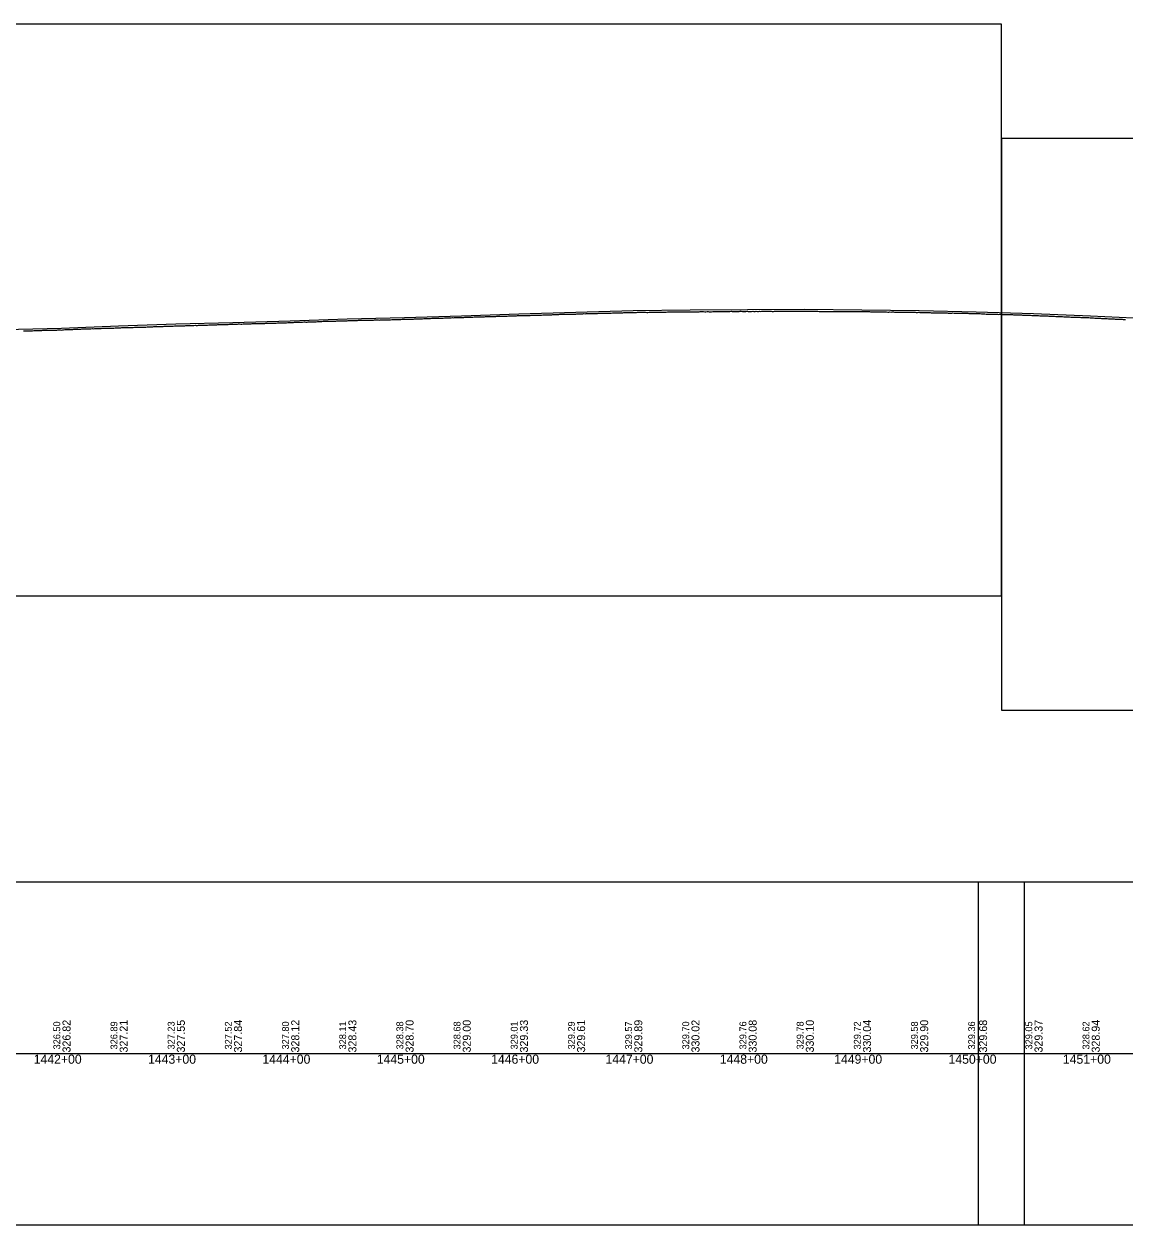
# Model space of a CAD drawing. Extents: x 2898 to 49495, y -15038 to -13538.
# Drawn here: x 33621 to 34583, y -15038 to -13988 of the extents above; entities that cross this region are included whole.
import ezdxf

# ---------------------------------------------------------------- set-up
doc = ezdxf.new("R2010")
doc.units = 0
for name, color, linetype in [('RD_DDB_Profile_EX', 7, 'Continuous'), ('RD_DDB_Profile_PR', 7, 'Continuous'), ('RD_DDB_StaTX', 7, 'Continuous'), ('RD_DDB_StripGrade', 7, 'Continuous'), ('RD_GPK_Profile_Cell', 7, 'Continuous'), ('RD_SHT_ShtClip', 7, 'Continuous')]:
    doc.layers.add(name, color=color, linetype=linetype)

msp = doc.modelspace()

# ---------------------------------------------------------------- linework, layer by layer
at = {"layer": 'RD_DDB_Profile_EX'}
for points in [[(33858.3, -14249.1), (33859.3, -14249.1), (33860.3, -14249.1), (33861.3, -14249.1), (33862.3, -14249.1), (33863.3, -14249.1), (33864.3, -14249), (33865.3, -14248.9), (33866.3, -14248.9), (33867.3, -14249), (33868.3, -14249), (33869.3, -14248.9), (33870.3, -14248.8), (33871.3, -14248.7), (33872.3, -14248.7), (33873.3, -14248.7), (33874.3, -14248.7), (33875.3, -14248.8), (33876.3, -14248.7), (33877.3, -14248.6), (33878.3, -14248.6), (33879.3, -14248.6), (33880.3, -14248.5), (33881.3, -14248.5), (33882.3, -14248.4), (33883.3, -14248.4), (33884.3, -14248.4), (33885.3, -14248.4), (33886.3, -14248.4), (33887.3, -14248.2), (33888.3, -14248.3), (33889.3, -14248.3), (33890.3, -14248.3), (33891.3, -14248.2), (33892.3, -14248.2), (33893.3, -14248.2), (33894.3, -14248.1), (33895.3, -14248), (33896.3, -14248), (33897.3, -14248), (33898.3, -14248), (33899.3, -14248), (33900.3, -14248), (33901.3, -14247.9), (33902.3, -14247.9), (33903.3, -14247.9), (33904.3, -14247.8), (33905.3, -14247.8), (33906.3, -14247.8), (33907.3, -14247.8), (33908.3, -14247.8), (33909.3, -14247.8), (33910.3, -14247.8), (33911.3, -14247.7), (33912.3, -14247.7), (33913.3, -14247.5), (33914.3, -14247.5), (33915.3, -14247.5), (33916.3, -14247.4), (33917.3, -14247.5), (33918.3, -14247.5), (33919.3, -14247.4), (33920.3, -14247.4), (33921.3, -14247.4), (33922.3, -14247.4), (33923.3, -14247.4), (33924.3, -14247.3), (33925.3, -14247.4), (33926.3, -14247.3), (33927.3, -14247.2), (33928.3, -14247.2), (33929.3, -14247.2), (33930.3, -14247.2), (33931.3, -14247.3), (33932.3, -14247.1), (33933.3, -14247.1), (33934.3, -14247.1), (33935.3, -14247.1), (33936.3, -14247.1), (33937.3, -14247), (33938.3, -14247), (33939.3, -14247.1), (33940.3, -14247.1), (33941.3, -14247), (33942.3, -14246.9), (33943.3, -14246.9), (33944.3, -14246.9), (33945.3, -14246.9), (33946.3, -14246.9), (33947.3, -14246.8), (33948.3, -14246.8), (33949.3, -14246.7), (33950.3, -14246.7), (33951.3, -14246.6), (33952.3, -14246.6), (33953.3, -14246.6), (33954.3, -14246.6), (33955.3, -14246.6), (33956.3, -14246.5), (33957.3, -14246.5), (33958.3, -14246.5)], [(33958.3, -14246.5), (33959.3, -14246.5), (33960.3, -14246.4), (33961.3, -14246.4), (33962.3, -14246.3), (33963.3, -14246.3), (33964.3, -14246.2), (33965.3, -14246.2), (33966.3, -14246.2), (33967.3, -14246.1), (33968.3, -14246.1), (33969.3, -14246.1), (33970.3, -14246), (33971.3, -14246), (33972.3, -14246), (33973.3, -14245.9), (33974.3, -14245.9), (33975.3, -14245.8), (33976.3, -14245.8), (33977.3, -14245.7), (33978.3, -14245.6), (33979.3, -14245.7), (33980.3, -14245.6), (33981.3, -14245.6), (33982.3, -14245.6), (33983.3, -14245.6), (33984.3, -14245.5), (33985.3, -14245.5), (33986.3, -14245.5), (33987.3, -14245.5), (33988.3, -14245.4), (33989.3, -14245.4), (33990.3, -14245.4), (33991.3, -14245.4), (33992.3, -14245.3), (33993.3, -14245.3), (33994.3, -14245.3), (33995.3, -14245.2), (33996.3, -14245.3), (33997.3, -14245.2), (33998.3, -14245.2), (33999.3, -14245.2), (34000.3, -14245.1), (34001.3, -14245.1), (34002.3, -14245.1), (34003.3, -14245.1), (34004.3, -14245), (34005.3, -14245), (34006.3, -14244.9), (34007.3, -14244.9), (34008.3, -14244.9), (34009.3, -14244.8), (34010.3, -14244.9), (34011.3, -14244.8), (34012.3, -14244.7), (34013.3, -14244.7), (34014.3, -14244.6), (34015.3, -14244.6), (34016.3, -14244.5), (34017.3, -14244.5), (34018.3, -14244.5), (34019.3, -14244.5), (34020.3, -14244.5), (34021.3, -14244.4), (34022.3, -14244.4), (34023.3, -14244.4), (34024.3, -14244.3), (34025.3, -14244.2), (34026.3, -14244.3), (34027.3, -14244.3), (34028.3, -14244.3), (34029.3, -14244.2), (34030.3, -14244.1), (34031.3, -14244.1), (34032.3, -14244.2), (34033.3, -14244.1), (34034.3, -14244), (34035.3, -14244), (34036.3, -14244), (34037.3, -14244), (34038.3, -14243.9), (34039.3, -14243.9), (34040.3, -14243.9), (34041.3, -14243.9), (34042.3, -14243.9), (34043.3, -14243.8), (34044.3, -14243.7), (34045.3, -14243.7), (34046.3, -14243.7), (34047.3, -14243.6), (34048.3, -14243.6), (34049.3, -14243.6), (34050.3, -14243.5), (34051.3, -14243.5), (34052.3, -14243.4), (34053.3, -14243.4), (34054.3, -14243.4), (34055.3, -14243.3), (34056.3, -14243.3), (34057.3, -14243.3), (34058.3, -14243.2)], [(34058.3, -14243.2), (34059.3, -14243.2), (34060.3, -14243.3), (34061.3, -14243.3), (34062.3, -14243.3), (34063.3, -14243.2), (34064.3, -14243.1), (34065.3, -14243.1), (34066.3, -14243.1), (34067.3, -14243.1), (34068.3, -14243.1), (34069.3, -14243.1), (34070.3, -14243), (34071.3, -14243), (34072.3, -14242.9), (34073.3, -14242.9), (34074.3, -14242.8), (34075.3, -14242.8), (34076.3, -14242.8), (34077.3, -14242.7), (34078.3, -14242.7), (34079.3, -14242.7), (34080.3, -14242.7), (34081.3, -14242.6), (34082.3, -14242.6), (34083.3, -14242.5), (34084.3, -14242.5), (34085.3, -14242.5), (34086.3, -14242.4), (34087.3, -14242.3), (34088.3, -14242.3), (34089.3, -14242.2), (34090.3, -14242.2), (34091.3, -14242.2), (34092.3, -14242.2), (34093.3, -14242.2), (34094.3, -14242.2), (34095.3, -14242.1), (34096.3, -14242.1), (34097.3, -14242), (34098.3, -14242.1), (34099.3, -14242.1), (34100.3, -14242), (34101.3, -14242), (34102.3, -14242), (34103.3, -14242), (34104.3, -14241.9), (34105.3, -14241.9), (34106.3, -14241.8), (34107.3, -14241.8), (34108.3, -14241.8), (34109.3, -14241.8), (34110.3, -14241.7), (34111.3, -14241.8), (34112.3, -14241.7), (34113.3, -14241.6), (34114.3, -14241.6), (34115.3, -14241.6), (34116.3, -14241.6), (34117.3, -14241.6), (34118.3, -14241.5), (34119.3, -14241.5), (34120.3, -14241.5), (34121.3, -14241.5), (34122.3, -14241.5), (34123.3, -14241.4), (34124.3, -14241.4), (34125.3, -14241.3), (34126.3, -14241.4), (34127.3, -14241.3), (34128.3, -14241.3), (34129.3, -14241.3), (34130.3, -14241.2), (34131.3, -14241.2), (34132.3, -14241.2), (34133.3, -14241.2), (34134.3, -14241.2), (34135.3, -14241.1), (34136.3, -14241.1), (34137.3, -14241.1), (34138.3, -14241.1), (34139.3, -14241), (34140.3, -14240.9), (34141.3, -14241), (34142.3, -14241), (34143.3, -14240.9), (34144.3, -14240.9), (34145.3, -14240.8), (34146.3, -14240.8), (34147.3, -14240.8), (34148.3, -14240.7), (34149.3, -14240.7), (34150.3, -14240.7), (34151.3, -14240.6), (34152.3, -14240.6), (34153.3, -14240.6), (34154.3, -14240.6), (34155.3, -14240.6), (34156.3, -14240.6), (34157.3, -14240.5), (34158.3, -14240.5)], [(34158.3, -14240.5), (34159.3, -14240.5), (34160.3, -14240.5), (34161.3, -14240.5), (34162.3, -14240.5), (34163.3, -14240.5), (34164.3, -14240.4), (34165.3, -14240.6), (34166.3, -14240.6), (34167.3, -14240.4), (34168.3, -14240.3), (34169.3, -14240.4), (34170.3, -14240.4), (34171.3, -14240.4), (34172.3, -14240.3), (34173.3, -14240.3), (34174.3, -14240.3), (34175.3, -14240.3), (34176.3, -14240.3), (34177.3, -14240.4), (34178.3, -14240.4), (34179.3, -14240.3), (34180.3, -14240.3), (34181.3, -14240.4), (34182.3, -14240.3), (34183.3, -14240.2), (34184.3, -14240.2), (34185.3, -14240.2), (34186.3, -14240.1), (34187.3, -14240.1), (34188.3, -14240.1), (34189.3, -14240.1), (34190.3, -14240.1), (34191.3, -14240.1), (34192.3, -14240.1), (34193, -14240.1), (34194, -14240.1), (34195, -14240.1), (34196, -14240.1), (34197, -14240), (34198, -14240), (34199, -14240), (34200, -14240), (34201, -14240.1), (34202, -14240), (34203, -14240), (34204, -14240), (34205, -14240), (34206, -14240), (34207, -14240), (34208, -14240.1), (34209, -14240.1), (34210, -14240), (34211, -14240), (34212, -14239.9), (34213, -14239.9), (34214, -14239.9), (34215, -14239.9), (34216, -14240), (34217, -14240), (34218, -14239.8), (34219, -14239.9), (34220, -14240), (34221, -14240), (34222, -14240), (34223, -14239.9), (34224, -14239.9), (34225, -14239.9), (34226, -14239.8), (34227, -14239.8), (34228, -14239.8), (34229, -14239.9), (34230, -14239.9), (34231, -14239.9), (34232, -14239.9), (34233, -14239.8), (34234, -14239.8), (34235, -14239.8), (34236, -14239.8), (34237, -14239.8), (34238, -14239.7), (34239, -14239.6), (34240, -14239.7), (34241, -14239.7), (34242, -14239.7), (34243, -14239.7), (34244, -14239.7), (34245, -14239.7), (34246, -14239.7), (34247, -14239.6), (34248, -14239.6), (34249, -14239.7), (34250, -14239.7), (34251, -14239.7), (34252, -14239.7), (34253, -14239.6), (34254, -14239.7), (34255, -14239.7), (34256, -14239.7), (34257, -14239.7), (34258, -14239.6)], [(34258, -14239.6), (34259, -14239.7), (34260, -14239.7), (34261, -14239.6), (34262, -14239.7), (34263, -14239.7), (34264, -14239.6), (34265, -14239.7), (34266, -14239.6), (34267, -14239.6), (34268, -14239.6), (34269, -14239.6), (34270, -14239.6), (34271, -14239.6), (34272, -14239.6), (34273, -14239.6), (34274, -14239.6), (34275, -14239.7), (34276, -14239.7), (34277, -14239.6), (34278, -14239.5), (34279, -14239.5), (34280, -14239.6), (34281, -14239.6), (34282, -14239.6), (34283, -14239.5), (34284, -14239.6), (34285, -14239.6), (34286, -14239.6), (34287, -14239.6), (34288, -14239.6), (34289, -14239.6), (34290, -14239.5), (34291, -14239.5), (34292, -14239.5), (34293, -14239.6), (34294, -14239.6), (34295, -14239.5), (34296, -14239.5), (34297, -14239.5), (34298, -14239.5), (34299, -14239.5), (34300, -14239.5), (34301, -14239.5), (34302, -14239.6), (34303, -14239.5), (34304, -14239.6), (34305, -14239.6), (34306, -14239.6), (34307, -14239.6), (34308, -14239.6), (34309, -14239.6), (34310, -14239.6), (34311, -14239.6), (34312, -14239.5), (34313, -14239.6), (34314, -14239.6), (34315, -14239.6), (34316, -14239.7), (34317, -14239.7), (34318, -14239.7), (34319, -14239.7), (34320, -14239.8), (34321, -14239.8), (34322, -14239.8), (34323, -14239.8), (34324, -14239.7), (34325, -14239.7), (34326, -14239.7), (34327, -14239.7), (34328, -14239.8), (34329, -14239.8), (34330, -14239.7), (34331, -14239.7), (34332, -14239.7), (34333, -14239.7), (34334, -14239.7), (34335, -14239.7), (34336, -14239.7), (34337, -14239.7), (34338, -14239.8), (34339, -14239.8), (34340, -14239.7), (34341, -14239.7), (34342, -14239.7), (34343, -14239.7), (34344, -14239.7), (34345, -14239.8), (34346, -14239.8), (34347, -14239.8), (34348, -14239.8), (34349, -14239.8), (34350, -14239.8), (34351, -14239.9), (34352, -14239.9), (34353, -14239.9), (34354, -14239.9), (34355, -14239.8), (34356, -14239.8), (34357, -14239.9), (34358, -14239.9)], [(34358, -14239.9), (34359, -14239.9), (34360, -14239.9), (34361, -14240), (34362, -14240), (34363, -14240), (34364, -14240), (34365, -14240), (34366, -14240), (34367, -14240), (34368, -14240), (34369, -14240.1), (34370, -14240.1), (34371, -14240.1), (34372, -14240.1), (34373, -14240.2), (34374, -14240.2), (34375, -14240.2), (34376, -14240.3), (34377, -14240.3), (34378, -14240.2), (34379, -14240.3), (34380, -14240.2), (34381, -14240.2), (34382, -14240.3), (34383, -14240.3), (34384, -14240.3), (34385, -14240.4), (34386, -14240.4), (34387, -14240.4), (34388, -14240.4), (34389, -14240.4), (34390, -14240.4), (34391, -14240.4), (34392, -14240.4), (34393, -14240.4), (34394, -14240.4), (34395, -14240.4), (34396, -14240.4), (34397, -14240.4), (34398, -14240.4), (34399, -14240.5), (34400, -14240.5), (34401, -14240.6), (34402, -14240.6), (34403, -14240.5), (34404, -14240.6), (34405, -14240.7), (34406, -14240.7), (34407, -14240.7), (34408, -14240.7), (34409, -14240.7), (34410, -14240.7), (34411, -14240.8), (34412, -14240.8), (34413, -14240.8), (34414, -14240.9), (34415, -14240.9), (34416, -14240.9), (34417, -14240.9), (34418, -14240.9), (34419, -14241), (34420, -14241), (34421, -14241), (34422, -14241), (34423, -14241), (34424, -14241), (34425, -14241), (34426, -14241), (34427, -14241.1), (34428, -14241.1), (34429, -14241.2), (34430, -14241.3), (34431, -14241.2), (34432, -14241.2), (34433, -14241.1), (34434, -14241.2), (34435, -14241.3), (34436, -14241.4), (34437, -14241.4), (34438, -14241.4), (34439, -14241.4), (34440, -14241.4), (34441, -14241.4), (34442, -14241.4), (34443, -14241.4), (34444, -14241.4), (34445, -14241.4), (34446, -14241.4), (34447, -14241.5), (34448, -14241.5), (34449, -14241.5), (34450, -14241.5), (34451, -14241.5), (34452, -14241.6), (34453, -14241.6), (34454, -14241.7), (34455, -14241.6), (34456, -14241.7), (34457, -14241.7), (34458, -14241.8)], [(34458, -14241.8), (34459, -14241.8), (34460, -14241.9), (34461, -14241.9), (34462, -14242), (34463, -14242), (34464, -14242), (34465, -14242), (34466, -14242), (34467, -14242), (34468, -14242), (34469, -14242.1), (34470, -14242.2), (34471, -14242.2), (34472, -14242.2), (34473, -14242.3), (34474, -14242.2), (34475, -14242.2), (34476, -14242.3), (34477, -14242.4), (34478, -14242.4), (34479, -14242.4), (34480, -14242.4), (34481, -14242.4), (34482, -14242.5), (34483, -14242.5), (34484, -14242.5), (34485, -14242.5), (34486, -14242.6), (34487, -14242.6), (34488, -14242.6), (34489, -14242.7), (34490, -14242.8), (34491, -14242.7), (34492, -14242.8), (34493, -14242.8), (34494, -14242.9), (34495, -14242.9), (34496, -14243), (34497, -14243), (34498, -14243.1), (34499, -14243.1), (34500, -14243.1), (34501, -14243.1), (34502, -14243.2), (34503, -14243.2), (34504, -14243.2), (34505, -14243.3), (34506, -14243.3), (34507, -14243.4), (34508, -14243.4), (34509, -14243.5), (34510, -14243.5), (34511, -14243.5), (34512, -14243.6), (34513, -14243.6), (34514, -14243.7), (34515, -14243.7), (34516, -14243.7), (34517, -14243.8), (34518, -14243.8), (34519, -14243.8), (34520, -14243.9), (34521, -14243.9), (34522, -14244), (34523, -14244.1), (34524, -14244.2), (34525, -14244.1), (34526, -14244.1), (34527, -14244.2), (34528, -14244.3), (34529, -14244.3), (34530, -14244.4), (34531, -14244.4), (34532, -14244.4), (34533, -14244.5), (34534, -14244.5), (34535, -14244.5), (34536, -14244.7), (34537, -14244.7), (34538, -14244.7), (34539, -14244.8), (34540, -14244.8), (34541, -14244.8), (34542, -14244.8), (34543, -14244.8), (34544, -14244.9), (34545, -14245), (34546, -14245), (34547, -14245), (34548, -14245.1), (34549, -14245.1), (34550, -14245.1), (34551, -14245.1), (34552, -14245.2), (34553, -14245.3), (34554, -14245.4), (34555, -14245.4), (34556, -14245.4), (34557, -14245.5), (34558, -14245.5)], [(34558, -14245.5), (34559, -14245.5), (34560, -14245.6), (34561, -14245.7), (34562, -14245.7), (34563, -14245.8), (34564, -14245.8), (34565, -14245.8), (34566, -14245.9), (34567, -14246), (34568, -14246), (34569, -14246.1), (34570, -14246.1), (34571, -14246.2), (34572, -14246.3), (34573, -14246.3), (34574, -14246.3), (34575, -14246.4), (34576, -14246.4), (34577, -14246.5), (34578, -14246.6), (34579, -14246.6), (34580, -14246.6), (34581, -14246.6), (34582, -14246.7), (34583, -14246.7), (34584, -14246.8)], [(33620.3, -14256.7), (33621.3, -14256.7), (33622.3, -14256.7), (33623.3, -14256.7), (33624.3, -14256.6), (33625.3, -14256.7), (33626.3, -14256.6), (33627.3, -14256.6), (33628.3, -14256.6), (33629.3, -14256.5), (33630.3, -14256.5), (33631.3, -14256.5), (33632.3, -14256.4), (33633.3, -14256.3), (33634.3, -14256.4), (33635.3, -14256.3), (33636.3, -14256.3), (33637.3, -14256.2), (33638.3, -14256.2), (33639.3, -14256.2), (33640.3, -14256.2), (33641.3, -14256.1), (33642.3, -14256.1), (33643.3, -14256.2), (33644.3, -14256), (33645.3, -14256), (33646.3, -14256), (33647.3, -14256), (33648.3, -14256), (33649.3, -14256), (33650.3, -14255.8), (33651.3, -14255.9), (33652.3, -14255.9), (33653.3, -14256), (33654.3, -14255.9), (33655.3, -14255.7), (33656.3, -14255.6), (33657.3, -14255.6), (33658.3, -14255.6)], [(33658.3, -14255.6), (33659.3, -14255.5), (33660.3, -14255.5), (33661.3, -14255.5), (33662.3, -14255.5), (33663.3, -14255.5), (33664.3, -14255.4), (33665.3, -14255.4), (33666.3, -14255.3), (33667.3, -14255.3), (33668.3, -14255.3), (33669.3, -14255.2), (33670.3, -14255.2), (33671.3, -14255.1), (33672.3, -14255.1), (33673.3, -14255.1), (33674.3, -14255), (33675.3, -14254.9), (33676.3, -14254.9), (33677.3, -14254.9), (33678.3, -14254.9), (33679.3, -14254.9), (33680.3, -14254.8), (33681.3, -14254.9), (33682.3, -14254.8), (33683.3, -14254.8), (33684.3, -14254.7), (33685.3, -14254.7), (33686.3, -14254.6), (33687.3, -14254.6), (33688.3, -14254.6), (33689.3, -14254.5), (33690.3, -14254.5), (33691.3, -14254.5), (33692.3, -14254.5), (33693.3, -14254.5), (33694.3, -14254.4), (33695.3, -14254.4), (33696.3, -14254.3), (33697.3, -14254.3), (33698.3, -14254.3), (33699.3, -14254.3), (33700.3, -14254.2), (33701.3, -14254.1), (33702.3, -14254.1), (33703.3, -14254), (33704.3, -14254.1), (33705.3, -14254), (33706.3, -14253.9), (33707.3, -14253.9), (33708.3, -14253.8), (33709.3, -14253.8), (33710.3, -14253.8), (33711.3, -14253.8), (33712.3, -14253.7), (33713.3, -14253.7), (33714.3, -14253.7), (33715.3, -14253.7), (33716.3, -14253.7), (33717.3, -14253.6), (33718.3, -14253.5), (33719.3, -14253.5), (33720.3, -14253.6), (33721.3, -14253.6), (33722.3, -14253.5), (33723.3, -14253.4), (33724.3, -14253.4), (33725.3, -14253.4), (33726.3, -14253.4), (33727.3, -14253.4), (33728.3, -14253.3), (33729.3, -14253.1), (33730.3, -14253.1), (33731.3, -14253.1), (33732.3, -14253.2), (33733.3, -14253.1), (33734.3, -14253), (33735.3, -14253), (33736.3, -14253), (33737.3, -14253), (33738.3, -14252.9), (33739.3, -14252.9), (33740.3, -14252.9), (33741.3, -14252.8), (33742.3, -14252.8), (33743.3, -14252.7), (33744.3, -14252.7), (33745.3, -14252.7), (33746.3, -14252.6), (33747.3, -14252.6), (33748.3, -14252.6), (33749.3, -14252.5), (33750.3, -14252.5), (33751.3, -14252.5), (33752.3, -14252.4), (33753.3, -14252.3), (33754.3, -14252.3), (33755.3, -14252.3), (33756.3, -14252.4), (33757.3, -14252.4), (33758.3, -14252.3)], [(33758.3, -14252.3), (33759.3, -14252.2), (33760.3, -14252.2), (33761.3, -14252.2), (33762.3, -14252.1), (33763.3, -14252.1), (33764.3, -14252.1), (33765.3, -14252.1), (33766.3, -14252), (33767.3, -14252), (33768.3, -14252), (33769.3, -14252), (33770.3, -14251.9), (33771.3, -14252), (33772.3, -14252), (33773.3, -14251.9), (33774.3, -14251.8), (33775.3, -14251.9), (33776.3, -14251.8), (33777.3, -14251.8), (33778.3, -14251.7), (33779.3, -14251.7), (33780.3, -14251.7), (33781.3, -14251.7), (33782.3, -14251.5), (33783.3, -14251.5), (33784.3, -14251.5), (33785.3, -14251.4), (33786.3, -14251.4), (33787.3, -14251.4), (33788.3, -14251.4), (33789.3, -14251.4), (33790.3, -14251.3), (33791.3, -14251.3), (33792.3, -14251.2), (33793.3, -14251.2), (33794.3, -14251.1), (33795.3, -14251.1), (33796.3, -14251.1), (33797.3, -14251.1), (33798.3, -14251.1), (33799.3, -14251.1), (33800.3, -14251), (33801.3, -14251), (33802.3, -14251), (33803.3, -14250.9), (33804.3, -14250.9), (33805.3, -14250.8), (33806.3, -14250.8), (33807.3, -14250.8), (33808.3, -14250.7), (33809.3, -14250.7), (33810.3, -14250.8), (33811.3, -14250.8), (33812.3, -14250.7), (33813.3, -14250.6), (33814.3, -14250.6), (33815.3, -14250.6), (33816.3, -14250.6), (33817.3, -14250.5), (33818.3, -14250.6), (33819.3, -14250.5), (33820.3, -14250.4), (33821.3, -14250.4), (33822.3, -14250.4), (33823.3, -14250.3), (33824.3, -14250.3), (33825.3, -14250.3), (33826.3, -14250.3), (33827.3, -14250.3), (33828.3, -14250.3), (33829.3, -14250.3), (33830.3, -14250.2), (33831.3, -14250.2), (33832.3, -14250.1), (33833.3, -14250.1), (33834.3, -14250.1), (33835.3, -14250), (33836.3, -14250), (33837.3, -14250), (33838.3, -14250), (33839.3, -14250), (33840.3, -14249.9), (33841.3, -14249.9), (33842.3, -14249.8), (33843.3, -14249.8), (33844.3, -14249.7), (33845.3, -14249.7), (33846.3, -14249.7), (33847.3, -14249.6), (33848.3, -14249.6), (33849.3, -14249.6), (33850.3, -14249.6), (33851.3, -14249.5), (33852.3, -14249.5), (33853.3, -14249.5), (33854.3, -14249.4), (33855.3, -14249.4), (33856.3, -14249.3), (33857.3, -14249.2), (33858.3, -14249.1)]]:
    msp.add_lwpolyline(points, dxfattribs=at)
at = {"layer": 'RD_DDB_Profile_PR'}
msp.add_lwpolyline([(33603.4, -14255.6), (33653.4, -14254.4), (33703.4, -14252.4), (33753.4, -14250.7), (33803.4, -14249.3), (33853.4, -14247.9), (33903.4, -14246.3), (33953.4, -14245), (34003.4, -14243.5), (34053.4, -14241.8), (34103.4, -14240.4), (34153.4, -14239), (34203.4, -14238.4), (34253.4, -14238), (34303.4, -14237.9), (34353.4, -14238.3), (34403.4, -14239), (34453.4, -14240), (34503.4, -14241.6), (34553.4, -14243.7), (34603.4, -14246)], dxfattribs=at)
at = {"layer": 'RD_GPK_Profile_Cell'}
msp.add_line((2976.1, -14888.5), (48721.1, -14888.5), dxfattribs=at)
at = {"layer": 'RD_SHT_ShtClip'}
for points in [[(32975.4, -13988.5), (32975.4, -14488.5), (34475.4, -14488.5), (34475.4, -14488.5), (34475.4, -13988.5), (34475.4, -13988.5)], [(34475.4, -14088.5), (34475.4, -14588.5), (35975.4, -14588.5), (35975.4, -14588.5), (35975.4, -14088.5), (35975.4, -14088.5)], [(32955.4, -14738.5), (34495.4, -14738.5), (34495.4, -15038.5), (32955.4, -15038.5)], [(34455.4, -14738.5), (35995.4, -14738.5), (35995.4, -15038.5), (34455.4, -15038.5)]]:
    msp.add_lwpolyline(points, close=True, dxfattribs=at)

# ---------------------------------------------------------------- texts
at = {"layer": 'RD_DDB_StaTX'}
for s, p in [('1442+00', (33629.2, -14897.5)), ('1443+00', (33729.2, -14897.5)), ('1444+00', (33829.2, -14897.5)), ('1445+00', (33929.2, -14897.5)), ('1446+00', (34029.2, -14897.5)), ('1447+00', (34129.2, -14897.5)), ('1448+00', (34229.2, -14897.5)), ('1449+00', (34329.2, -14897.5)), ('1450+00', (34429.2, -14897.5)), ('1451+00', (34529.2, -14897.5))]:
    msp.add_text(s, height=8, dxfattribs=at).set_placement(p)
at = {"layer": 'RD_DDB_StripGrade'}
for s, height, p in [('326.50', 6, (33652.4, -14885)), ('326.82', 7, (33661.4, -14887.7)), ('326.89', 6, (33702.4, -14885)), ('327.21', 7, (33711.4, -14887.7)), ('327.23', 6, (33752.4, -14885)), ('327.55', 7, (33761.4, -14887.7)), ('327.52', 6, (33802.4, -14885)), ('327.84', 7, (33811.4, -14887.7)), ('327.80', 6, (33852.4, -14885)), ('328.12', 7, (33861.4, -14887.7)), ('328.11', 6, (33902.4, -14885)), ('328.43', 7, (33911.4, -14887.7)), ('328.38', 6, (33952.4, -14885)), ('328.70', 7, (33961.4, -14887.7)), ('328.68', 6, (34002.4, -14885)), ('329.00', 7, (34011.4, -14887.7)), ('329.01', 6, (34052.4, -14885)), ('329.33', 7, (34061.4, -14887.7)), ('329.29', 6, (34102.4, -14885)), ('329.61', 7, (34111.4, -14887.7)), ('329.57', 6, (34152.4, -14885)), ('329.89', 7, (34161.4, -14887.7)), ('329.70', 6, (34202.4, -14885)), ('330.02', 7, (34211.4, -14887.7)), ('329.76', 6, (34252.4, -14885)), ('330.08', 7, (34261.4, -14887.7)), ('329.78', 6, (34302.4, -14885)), ('330.10', 7, (34311.4, -14887.7)), ('329.72', 6, (34352.4, -14885)), ('330.04', 7, (34361.4, -14887.7)), ('329.58', 6, (34402.4, -14885)), ('329.90', 7, (34411.4, -14887.7)), ('329.36', 6, (34452.4, -14885)), ('329.68', 7, (34462.9, -14887.7)), ('329.05', 6, (34502.4, -14885)), ('329.37', 7, (34511.4, -14887.7)), ('328.62', 6, (34552.4, -14885)), ('328.94', 7, (34561.4, -14887.7))]:
    msp.add_text(s, height=height, rotation=90, dxfattribs=at).set_placement(p)

doc.saveas('drawing.dxf')
